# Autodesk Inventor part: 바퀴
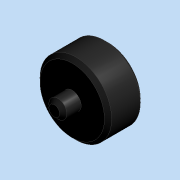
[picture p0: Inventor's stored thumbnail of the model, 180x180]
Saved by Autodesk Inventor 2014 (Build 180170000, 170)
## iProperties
Company: 한국ATC센터
Created: 2015-05
Part Number: 바퀴
Document SubType Name: 모델링
Designer: KYOUNG IL JANG
Vendor: CBT Solutions
Material: 일반
Appearance: 기본값
d0: 1.000 ul
Author: KYOUNG IL JANG
Comments: 파생
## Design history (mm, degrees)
derived "바퀴.ipt" dims count "d0" = 1
node "솔리드1"
node "솔리드 본체"
node "곡면 본체"
feature "솔리드1::바퀴.ipt" dims count "d0" = 1
tag "피쳐 태그1"
